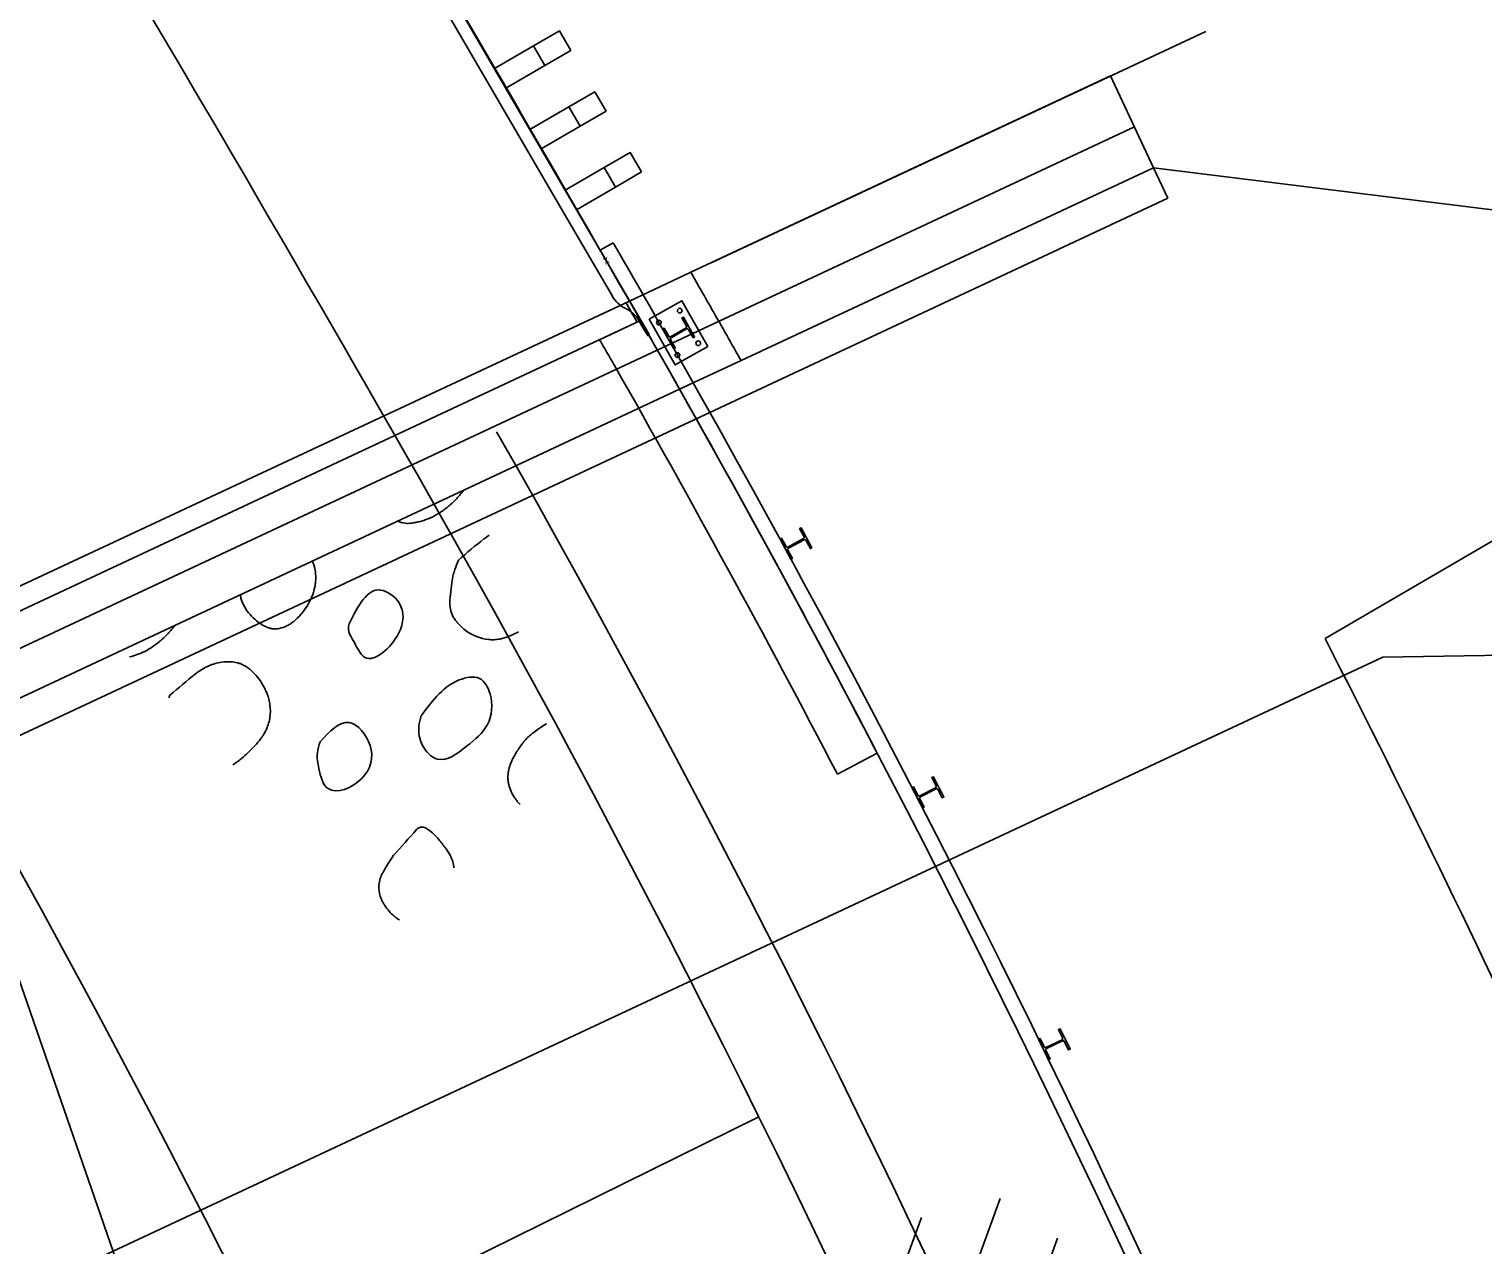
# Model space of a CAD drawing. Extents: x 2355002 to 2355569, y 708374 to 709566.
# Drawn here: x 2355330.68 to 2355362.95, y 709344.57 to 709371.58 of the extents above; entities that cross this region are included whole.
import ezdxf

# ---------------------------------------------------------------- set-up
doc = ezdxf.new("R2010")
doc.units = 0
for name, color, linetype in [('BD_X_Building', 7, 'Continuous'), ('BR_P_Sub_Const_Joint', 7, 'Continuous'), ('BR_X_Brg_Centerline', 7, 'Continuous'), ('BR_X_Det_Centerline', 7, 'Continuous'), ('BR_X_Gen_Approach_Slab', 7, 'Continuous'), ('BR_X_Rail_Stl_Det', 7, 'Continuous'), ('BR_X_Slab_Object', 7, 'Continuous'), ('BR_X_SV_Deck_Top', 7, 'Continuous'), ('DR_X_Cells', 7, 'Continuous'), ('DT_X_Slope_Break_Line', 7, 'Continuous'), ('GK_Drainage_Nodes', 7, 'Continuous'), ('HY_X_Wetland_Area', 7, 'Continuous'), ('PM_X_CL_Double_Solid', 7, 'Continuous'), ('PM_X_Edge_Line', 7, 'Continuous'), ('PM_X_Stop_Line', 7, 'Continuous'), ('RD_X_Concrete_Pad', 7, 'Continuous'), ('RD_X_GR_Lt', 7, 'Continuous'), ('RD_X_RR_Cells', 7, 'Continuous'), ('RD_X_Wall', 7, 'Continuous'), ('SN_X_Private', 7, 'Continuous'), ('UT_X_Unknown_Cells', 7, 'Continuous'), ('VG_X_Cells', 7, 'Continuous'), ('VG_X_Tree_Line_Rt', 7, 'Continuous')]:
    doc.layers.add(name, color=color, linetype=linetype)

msp = doc.modelspace()

# ---------------------------------------------------------------- linework, layer by layer
at = {"layer": 'BD_X_Building'}
msp.add_line((2355325.355, 709336.796), (2355346.875, 709347.42), dxfattribs=at)
msp.add_arc((2355104.75, 709227.886), 272.024, 5.4603, 29.69206, dxfattribs=at)
at = {"layer": 'BR_P_Sub_Const_Joint'}
msp.add_line((2355345.554, 709365.846), (2355345.366, 709366.175), dxfattribs=at)
for centre, radius, start, end in [((2354704.755, 708999.811), 737.974, 29.691502, 29.735666), ((2355104.75, 709227.887), 277.523, 29.41807, 29.6913)]:
    msp.add_arc(centre, radius, start, end, dxfattribs=at)
at = {"layer": 'BR_X_Brg_Centerline'}
msp.add_line((2355305.852, 709346.301), (2355355.213, 709369.404), dxfattribs=at)
at = {"layer": 'BR_X_Det_Centerline'}
msp.add_line((2355360.141, 709264.65), (2355328.268, 709356.793), dxfattribs=at)
at = {"layer": 'BR_X_Gen_Approach_Slab'}
msp.add_line((2355311.533, 709349.788), (2355344.252, 709365.102), dxfattribs=at)
msp.add_arc((2354704.756, 708999.812), 736.472, 29.735627, 32.069293, dxfattribs=at)
at = {"layer": 'BR_X_Rail_Stl_Det'}
msp.add_line((2355343.645, 709366.833), (2355343.356, 709366.667), dxfattribs=at)
for points in [[(2355345.746, 709364.529), (2355345.169, 709365.543), (2355344.444, 709365.131), (2355345.022, 709364.117), (2355345.746, 709364.529)], [(2355345.272, 709364.98), (2355345.168, 709365.163), (2355345.201, 709365.181), (2355345.326, 709364.961)], [(2355344.918, 709364.679), (2355345.022, 709364.497), (2355344.989, 709364.478), (2355344.739, 709364.918), (2355344.772, 709364.937), (2355344.876, 709364.754)], [(2355344.916, 709364.743), (2355345.261, 709364.939)], [(2355345.274, 709364.916), (2355344.93, 709364.72)], [(2355345.326, 709364.961), (2355345.451, 709364.741), (2355345.419, 709364.722), (2355345.315, 709364.905)], [(2355347.522, 709360.007), (2355347.623, 709359.822), (2355347.589, 709359.804), (2355347.347, 709360.249), (2355347.38, 709360.267), (2355347.481, 709360.083)], [(2355347.521, 709360.071), (2355347.869, 709360.26)], [(2355347.881, 709360.301), (2355347.781, 709360.485), (2355347.814, 709360.503), (2355347.935, 709360.281)], [(2355347.935, 709360.281), (2355348.056, 709360.058), (2355348.023, 709360.04), (2355347.922, 709360.225)], [(2355347.882, 709360.237), (2355347.534, 709360.047)], [(2355350.813, 709354.769), (2355350.717, 709354.956), (2355350.751, 709354.973), (2355350.867, 709354.748)], [(2355350.448, 709354.483), (2355350.544, 709354.296), (2355350.51, 709354.279), (2355350.278, 709354.729), (2355350.312, 709354.747), (2355350.408, 709354.56)], [(2355350.448, 709354.547), (2355350.801, 709354.729)], [(2355350.813, 709354.705), (2355350.461, 709354.523)], [(2355350.867, 709354.748), (2355350.983, 709354.523), (2355350.949, 709354.505), (2355350.853, 709354.692)], [(2355353.62, 709349.172), (2355353.528, 709349.361), (2355353.562, 709349.377), (2355353.673, 709349.15)], [(2355353.248, 709348.895), (2355353.34, 709348.706), (2355353.306, 709348.689), (2355353.084, 709349.145), (2355353.118, 709349.161), (2355353.21, 709348.972)], [(2355353.25, 709348.958), (2355353.606, 709349.132)], [(2355353.618, 709349.108), (2355353.261, 709348.935)], [(2355353.673, 709349.15), (2355353.784, 709348.922), (2355353.75, 709348.905), (2355353.657, 709349.094)]]:
    msp.add_lwpolyline(points, dxfattribs=at)
for centre in [(2355344.658, 709365.06), (2355345.12, 709365.323), (2355345.532, 709364.599), (2355345.07, 709364.336)]:
    msp.add_circle(centre, 0.0521, dxfattribs=at)
for centre, radius, start, end in [((2354704.755, 708999.811), 736.807, 29.691748, 29.875968), ((2354704.755, 708999.811), 736.474, 29.691748, 29.875968), ((2354704.755, 708999.811), 736.474, 29.691748, 29.735666), ((2355104.75, 709227.887), 276.357, 8.80517, 29.69195), ((2355345.246, 709364.965), 0.0298, 299.6462, 29.6462), ((2355345.289, 709364.89), 0.0298, 29.6462, 119.6462), ((2355104.75, 709227.887), 276.024, 8.80517, 29.69195), ((2355104.75, 709227.887), 276.024, 8.80517, 29.69195), ((2355344.902, 709364.769), 0.0298, 209.6462, 299.6462), ((2355344.944, 709364.694), 0.0298, 119.6462, 209.6462), ((2355347.855, 709360.286), 0.0298, 298.5646, 28.5646), ((2355347.507, 709360.097), 0.0298, 208.5646, 298.5646), ((2355347.548, 709360.021), 0.0298, 118.5646, 208.5646), ((2355347.896, 709360.211), 0.0298, 28.5646, 118.5646), ((2355350.787, 709354.755), 0.0298, 297.2688, 27.2688), ((2355350.435, 709354.574), 0.0298, 207.2688, 297.2688), ((2355350.474, 709354.497), 0.0298, 117.2688, 207.2688), ((2355350.826, 709354.678), 0.0298, 27.2688, 117.2688), ((2355353.237, 709348.985), 0.0298, 205.973, 295.973), ((2355353.593, 709349.159), 0.0298, 295.973, 25.973), ((2355353.631, 709349.081), 0.0298, 25.973, 115.973), ((2355353.274, 709348.908), 0.0298, 115.973, 205.973), ((2355104.75, 709227.887), 240.024, 6.23645, 29.69194), ((2355104.75, 709227.887), 239.69, 6.23645, 29.69194)]:
    msp.add_arc(centre, radius, start, end, dxfattribs=at)
at = {"layer": 'BR_X_Slab_Object'}
msp.add_arc((2355104.75, 709227.887), 240.024, 6.69347, 29.69206, dxfattribs=at)
at = {"layer": 'BR_X_SV_Deck_Top'}
for p, q in [((2355344.003, 709365.537), (2355345.366, 709366.175)), ((2355345.119, 709363.576), (2355346.482, 709364.213))]:
    msp.add_line(p, q, dxfattribs=at)
at = {"layer": 'DR_X_Cells'}
for p, q in [((2355345.366, 709366.175), (2355354.683, 709370.536)), ((2355355.637, 709368.498), (2355354.683, 709370.536)), ((2355346.482, 709364.213), (2355355.637, 709368.498))]:
    msp.add_line(p, q, dxfattribs=at)
at = {"layer": 'DT_X_Slope_Break_Line'}
msp.add_line((2355345.821, 709366.388), (2355356.799, 709371.526), dxfattribs=at)
at = {"layer": 'GK_Drainage_Nodes'}
for p in [(2355355.637, 709368.498), (2355306.594, 709344.716)]:
    msp.add_line(p, (2355355.955, 709367.819), dxfattribs=at)
at = {"layer": 'HY_X_Wetland_Area'}
msp.add_lwpolyline([(2355402.731, 709358.025), (2355392.727, 709358.151), (2355360.724, 709357.63), (2355311.362, 709334.527), (2355296.582, 709319.103), (2355283.234, 709303.179), (2355271.55, 709272.489), (2355265.075, 709252.406)], dxfattribs=at)
at = {"layer": 'PM_X_CL_Double_Solid'}
msp.add_arc((2355104.75, 709227.886), 258.024, 5.4603, 29.69206, dxfattribs=at)
msp.add_arc((2355104.75, 709227.886), 258.024, 5.4603, 29.69206, dxfattribs=at)
at = {"layer": 'PM_X_Edge_Line'}
for centre, radius, start, end in [((2354704.744, 708999.831), 730.474, 29.689927, 32.450085), ((2355104.75, 709227.886), 270.024, 5.4603, 29.69206), ((2355104.75, 709227.886), 246.024, 5.4603, 29.69206)]:
    msp.add_arc(centre, radius, start, end, dxfattribs=at)
at = {"layer": 'PM_X_Stop_Line'}
msp.add_lwpolyline([(2355306.276, 709345.396), (2355290.879, 709324.489), (2355296.582, 709319.103), (2355311.362, 709334.527), (2355360.724, 709357.63), (2355392.727, 709358.151), (2355391.331, 709364.068), (2355355.637, 709368.498)], dxfattribs=at)
for points in [[(2355340.322, 709361.33), (2355340.25, 709361.239), (2355340.17, 709361.149), (2355340.081, 709361.061), (2355340.033, 709361.018), (2355339.983, 709360.975), (2355339.885, 709360.898), (2355339.787, 709360.831), (2355339.588, 709360.724), (2355339.387, 709360.65), (2355339.286, 709360.625), (2355339.235, 709360.615), (2355339.184, 709360.607), (2355339.023, 709360.603), (2355338.857, 709360.645)], [(2355336.968, 709359.76), (2355336.985, 709359.72), (2355336.999, 709359.679), (2355337.021, 709359.596), (2355337.042, 709359.431), (2355337.035, 709359.269), (2355337.022, 709359.19), (2355337.013, 709359.151), (2355337.003, 709359.113), (2355336.975, 709359.022), (2355336.94, 709358.934), (2355336.85, 709358.763), (2355336.731, 709358.601), (2355336.66, 709358.522), (2355336.621, 709358.483), (2355336.58, 709358.445), (2355336.545, 709358.416), (2355336.509, 709358.389), (2355336.434, 709358.341), (2355336.275, 709358.276), (2355336.115, 709358.256), (2355336.039, 709358.266), (2355336.002, 709358.276), (2355335.984, 709358.282), (2355335.967, 709358.289), (2355335.883, 709358.33), (2355335.803, 709358.38), (2355335.652, 709358.503), (2355335.522, 709358.653), (2355335.467, 709358.737), (2355335.443, 709358.781), (2355335.421, 709358.827), (2355335.388, 709358.917), (2355335.369, 709359.012)], [(2355341.539, 709358.193), (2355341.435, 709358.137), (2355341.331, 709358.091), (2355341.225, 709358.055), (2355341.172, 709358.041), (2355341.146, 709358.034), (2355341.119, 709358.029), (2355341.061, 709358.02), (2355341, 709358.015), (2355340.874, 709358.02), (2355340.613, 709358.085), (2355340.361, 709358.228), (2355340.246, 709358.329), (2355340.191, 709358.387), (2355340.165, 709358.418), (2355340.153, 709358.434), (2355340.14, 709358.45), (2355340.112, 709358.491), (2355340.088, 709358.532), (2355340.052, 709358.614), (2355340.019, 709358.779), (2355340.023, 709358.943), (2355340.032, 709359.025), (2355340.042, 709359.107), (2355340.056, 709359.225), (2355340.072, 709359.343), (2355340.095, 709359.459), (2355340.13, 709359.573), (2355340.211, 709359.782)], [(2355337.783, 709358.368), (2355338.48, 709359.119), (2355338.893, 709358.831), (2355338.879, 709358.156), (2355338.135, 709357.622), (2355337.861, 709358.024), (2355337.766, 709358.246), (2355337.783, 709358.368)], [(2355333.916, 709358.332), (2355333.844, 709358.24), (2355333.763, 709358.151), (2355333.675, 709358.063), (2355333.627, 709358.019), (2355333.577, 709357.977), (2355333.246, 709357.756), (2355332.909, 709357.633)], [(2355333.804, 709356.784), (2355334.37, 709357.255), (2355334.423, 709357.296), (2355334.481, 709357.335), (2355334.605, 709357.405), (2355334.878, 709357.502), (2355335.161, 709357.526), (2355335.297, 709357.505), (2355335.362, 709357.484), (2355335.394, 709357.472), (2355335.425, 709357.458), (2355335.516, 709357.405), (2355335.601, 709357.341), (2355335.749, 709357.187), (2355335.869, 709357.009), (2355335.918, 709356.915), (2355335.94, 709356.867), (2355335.961, 709356.82), (2355335.983, 709356.758), (2355336.002, 709356.695), (2355336.026, 709356.566), (2355336.025, 709356.299), (2355335.949, 709356.032), (2355335.882, 709355.904), (2355335.84, 709355.842), (2355335.793, 709355.781), (2355335.653, 709355.62), (2355335.507, 709355.476), (2355335.358, 709355.348), (2355335.282, 709355.291), (2355335.205, 709355.239)], [(2355339.383, 709356.324), (2355339.73, 709356.762), (2355340.227, 709357.121), (2355340.677, 709357.154), (2355340.911, 709356.814), (2355340.853, 709356.132), (2355340.387, 709355.649), (2355339.746, 709355.362), (2355339.407, 709355.68), (2355339.331, 709356.086), (2355339.383, 709356.324)], [(2355337.138, 709355.751), (2355337.782, 709356.176), (2355338.249, 709355.669), (2355338.064, 709354.933), (2355337.315, 709354.708), (2355337.111, 709355.155), (2355337.078, 709355.501), (2355337.138, 709355.751)], [(2355341.576, 709354.354), (2355341.516, 709354.426), (2355341.463, 709354.499), (2355341.379, 709354.648), (2355341.326, 709354.8), (2355341.313, 709354.878), (2355341.309, 709354.918), (2355341.308, 709354.957), (2355341.32, 709355.097), (2355341.359, 709355.24), (2355341.42, 709355.381), (2355341.498, 709355.517), (2355341.57, 709355.627), (2355341.643, 709355.729), (2355341.723, 709355.823), (2355341.815, 709355.905), (2355341.95, 709356.007)], [(2355338.769, 709353.228), (2355339.279, 709353.8), (2355339.295, 709353.817), (2355339.313, 709353.83), (2355339.35, 709353.848), (2355339.43, 709353.85), (2355339.606, 709353.749), (2355339.784, 709353.564), (2355339.866, 709353.461), (2355339.905, 709353.411), (2355339.941, 709353.363), (2355340.056, 709353.16), (2355340.113, 709352.95)], [(2355338.902, 709351.788), (2355338.84, 709351.831), (2355338.781, 709351.879), (2355338.671, 709351.987), (2355338.576, 709352.111), (2355338.535, 709352.178), (2355338.517, 709352.213), (2355338.499, 709352.248), (2355338.471, 709352.323), (2355338.444, 709352.561), (2355338.473, 709352.716), (2355338.501, 709352.789), (2355338.518, 709352.823), (2355338.537, 709352.856), (2355338.769, 709353.228)]]:
    msp.add_spline(points, degree=3, dxfattribs=at)
at = {"layer": 'RD_X_Concrete_Pad'}
for p, q in [((2355333.781, 709356.724), (2355333.804, 709356.784)), ((2355341.936, 709355.997), (2355342.16, 709356.152))]:
    msp.add_line(p, q, dxfattribs=at)
msp.add_spline([(2355340.211, 709359.782), (2355340.776, 709360.253), (2355340.888, 709360.335)], degree=3, dxfattribs=at)
at = {"layer": 'RD_X_GR_Lt'}
for p, q in [((2355344.252, 709365.102), (2355343.343, 709364.676)), ((2355348.619, 709355.032), (2355349.505, 709355.494))]:
    msp.add_line(p, q, dxfattribs=at)
for centre, radius, start, end in [((2354704.755, 708999.811), 736.474, 29.691503, 29.735666), ((2354704.755, 708999.811), 735.474, 29.691503, 29.742009), ((2354704.755, 708999.811), 735.474, 29.691503, 29.742009), ((2355104.75, 709227.887), 276.023, 27.53605, 29.6913), ((2355104.75, 709227.887), 275.024, 27.53605, 29.69195), ((2355104.75, 709227.887), 275.024, 27.53605, 29.69195)]:
    msp.add_arc(centre, radius, start, end, dxfattribs=at)
at = {"layer": 'RD_X_RR_Cells'}
for p, q in [((2355346.763, 709330.517), (2355352.231, 709345.606)), ((2355344.796, 709329.491), (2355350.484, 709345.187)), ((2355348.73, 709331.543), (2355353.508, 709344.727))]:
    msp.add_line(p, q, dxfattribs=at)
at = {"layer": 'RD_X_Wall'}
msp.add_arc((2355104.75, 709227.886), 258.024, 5.4603, 29.69206, dxfattribs=at)
at = {"layer": 'SN_X_Private'}
for p, q in [((2355330.922, 709388.041), (2355344.445, 709364.792)), ((2355342.463, 709367.64), (2355336.964, 709377.094)), ((2355343.248, 709366.289), (2355342.463, 709367.64)), ((2355342.463, 709367.64), (2355342.463, 709367.64)), ((2355343.625, 709365.642), (2355343.248, 709366.289)), ((2355343.248, 709366.289), (2355343.248, 709366.289)), ((2355343.903, 709365.381), (2355343.937, 709365.364)), ((2355344.283, 709364.987), (2355344.216, 709365.103)), ((2355344.445, 709364.792), (2355344.445, 709364.792)), ((2355344.202, 709364.65), (2355344.202, 709364.65)), ((2355344.591, 709364.54), (2355344.591, 709364.54)), ((2355344.348, 709364.398), (2355344.348, 709364.398))]:
    msp.add_line(p, q, dxfattribs=at)
for points in [[(2355342.701, 709371.104), (2355342.45, 709371.536), (2355341.874, 709371.201), (2355342.125, 709370.769)], [(2355342.125, 709370.769), (2355341.874, 709371.201), (2355341.009, 709370.699), (2355341.261, 709370.266)], [(2355343.487, 709369.754), (2355343.235, 709370.186), (2355342.659, 709369.851), (2355342.911, 709369.418)], [(2355342.911, 709369.418), (2355342.659, 709369.851), (2355341.795, 709369.348), (2355342.046, 709368.916)], [(2355344.272, 709368.403), (2355344.021, 709368.835), (2355343.445, 709368.5), (2355343.696, 709368.068)], [(2355343.696, 709368.068), (2355343.445, 709368.5), (2355342.58, 709367.997), (2355342.832, 709367.565)]]:
    msp.add_lwpolyline(points, close=True, dxfattribs=at)
msp.add_lwpolyline([(2355344.445, 709364.792), (2355344.409, 709364.771), (2355344.283, 709364.987)], dxfattribs=at)
for centre, start, end in [((2355344.201, 709365.977), 210.1833, 243.494), ((2355343.639, 709364.767), 30.1833, 63.494)]:
    msp.add_arc(centre, 0.667, start, end, dxfattribs=at)
at = {"layer": 'UT_X_Unknown_Cells'}
msp.add_arc((2354704.755, 708999.811), 736.39, 29.736194, 29.775227, dxfattribs=at)
at = {"layer": 'VG_X_Cells'}
for p, q in [((2355311.283, 709350.223), (2355344.003, 709365.537)), ((2355312.408, 709348.266), (2355345.119, 709363.576))]:
    msp.add_line(p, q, dxfattribs=at)
at = {"layer": 'VG_X_Tree_Line_Rt'}
msp.add_line((2355359.446, 709358.04), (2355369.761, 709364.07), dxfattribs=at)
msp.add_arc((2355104.75, 709227.887), 286.024, 22.2085, 27.0676, dxfattribs=at)

# ---------------------------------------------------------------- texts
at = {"layer": 'BD_X_Building'}
msp.add_text('X', height=0.14, rotation=25.0808, dxfattribs=at).set_placement((2355343.465, 709366.344))

doc.saveas('drawing.dxf')
